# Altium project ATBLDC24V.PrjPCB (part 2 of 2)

## Sheet ATBLDC24V_Flash_Temp.SchDoc: ATBLDC24V_schematic
size A3; Organization: ATMEL Chennai; Address1: 12th Floor; Address2: Prince Infocity II; Address3: 283 & 284 OMR; Revision: 2; SheetNumber: 8; SheetTotal: 9; CheckedBy: MSK; DrawnBy: SAN/OJS; Engineer: SAN/OJS; PageSetup: Record=PageOptions¦CenterHorizontal=True¦CenterVertical=True¦PrintScale=1.01¦XCorrection=1.00¦YCorrection=1.00¦PrintKind=1¦BorderSize=5000000¦LeftOffset=0¦BottomOffset=0¦Orientation=2¦PaperLength=1000¦PaperWidth=1000¦Scale=100¦PaperSource=7¦PrintQuality=-4¦MediaType=1¦DitherType=10¦PaperKind=A3 (297 x 420 mm)¦PrintScaleMode=1
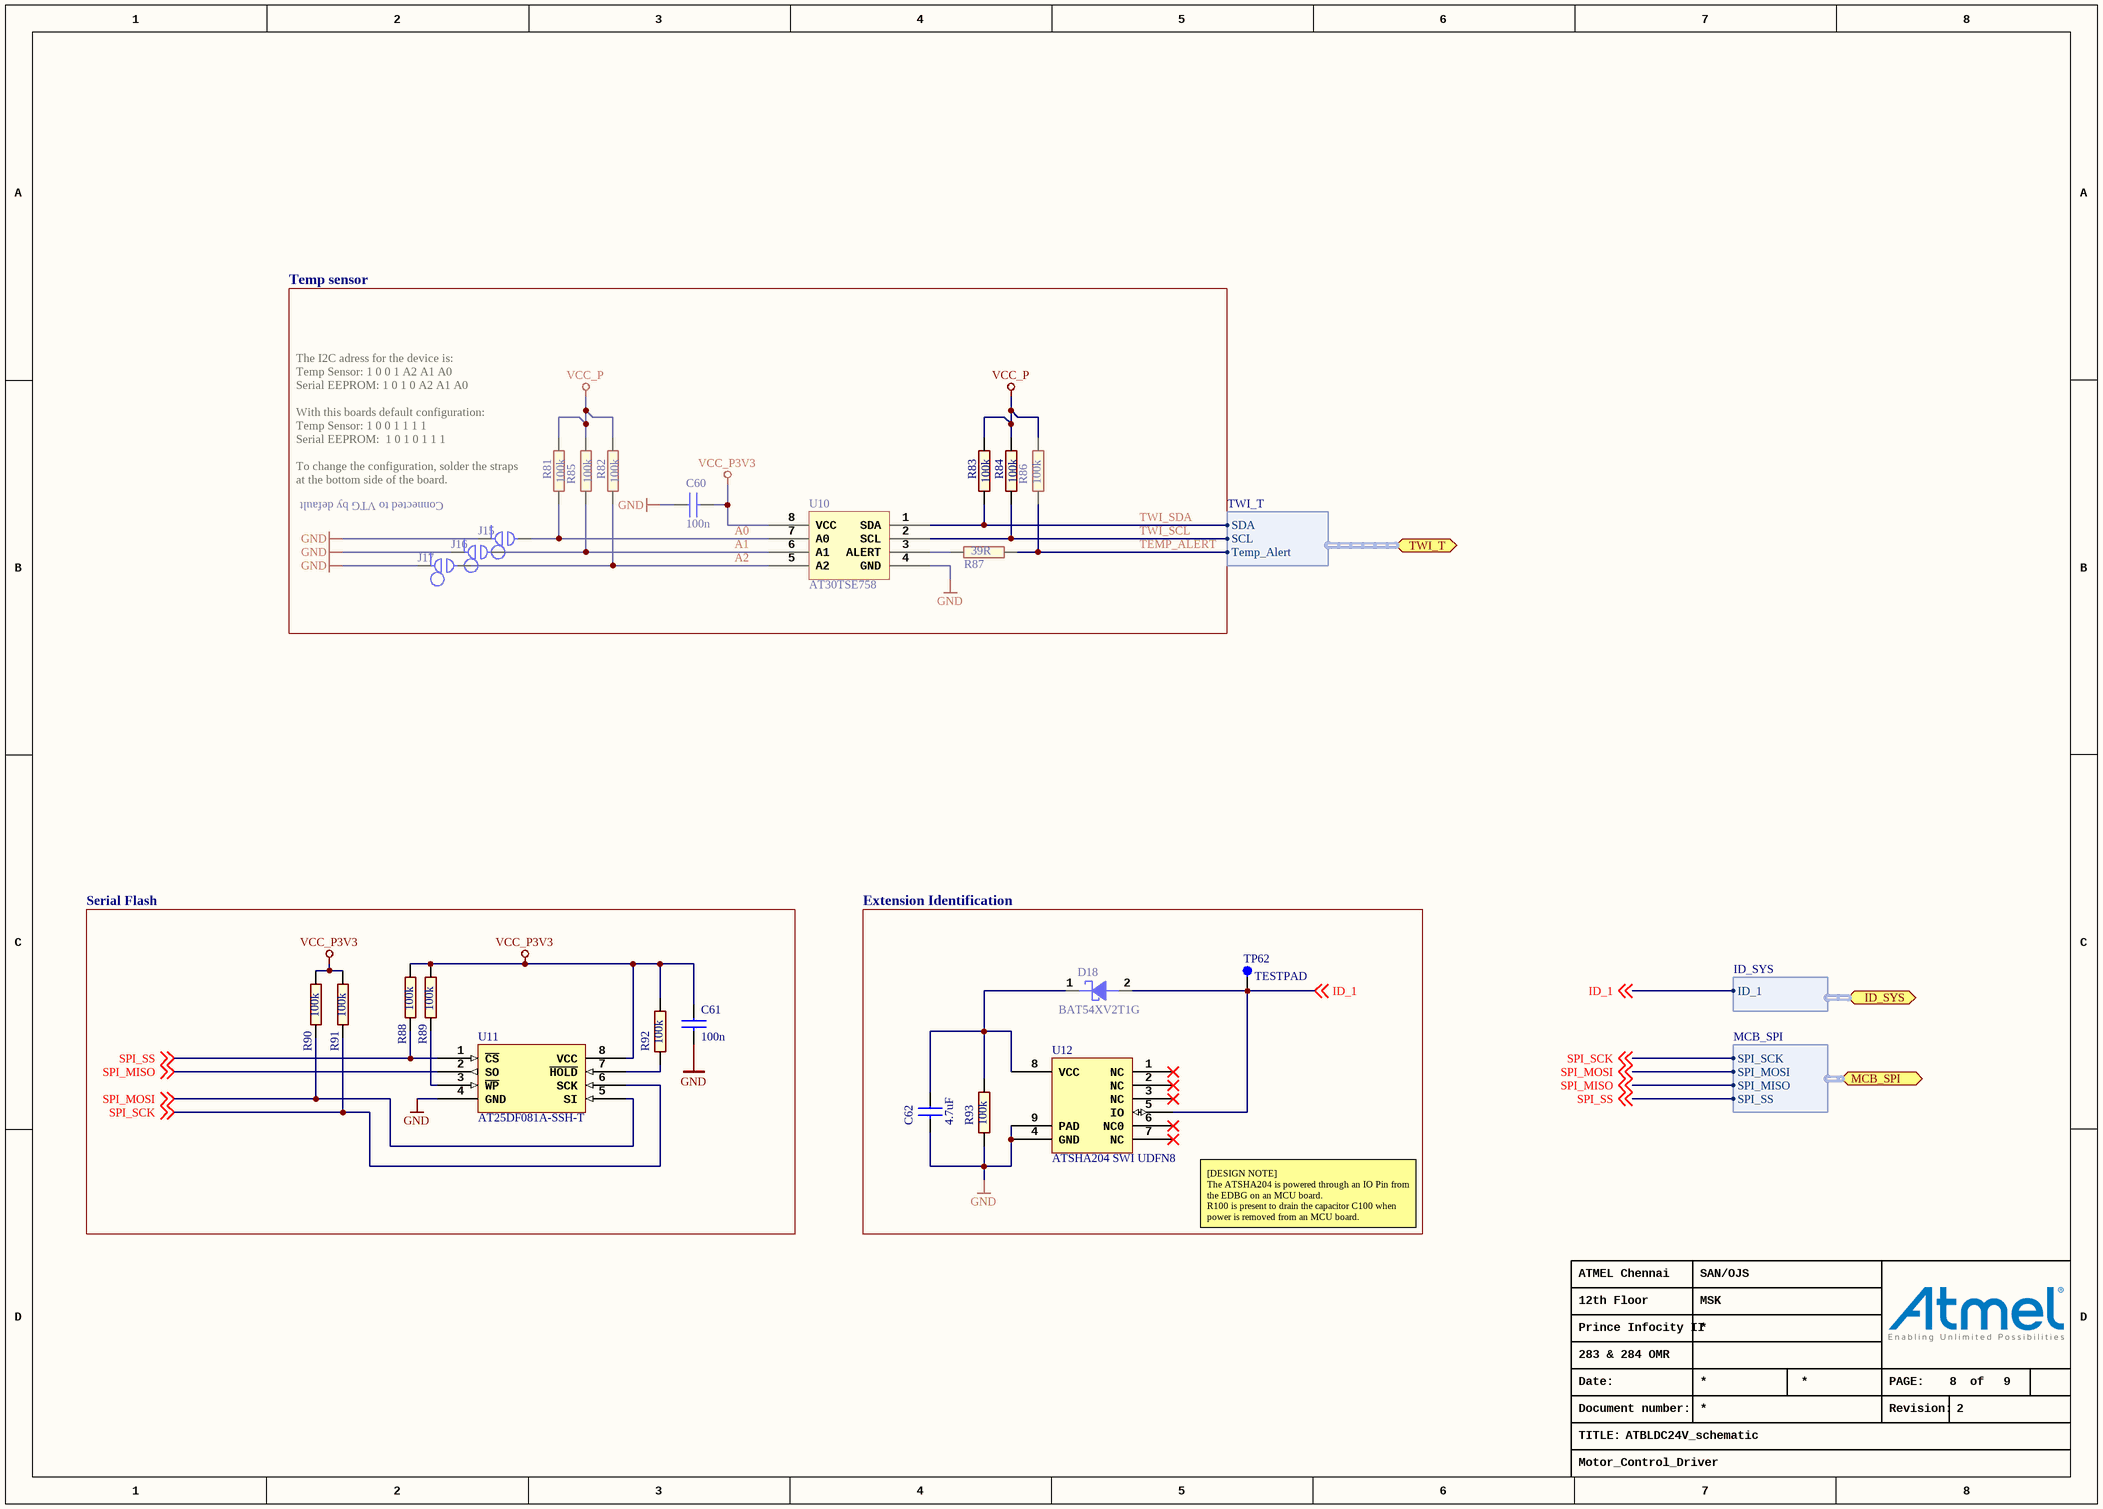
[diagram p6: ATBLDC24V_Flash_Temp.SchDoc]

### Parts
C60  100n  [AP1-00001]
C61  100n  [AP1-00001]
C62  value 4.7uF  [AP1-00001]  (hidden comment: Recommended by Escatec. No datasheet available yet.)
D18  value BAT54XV2T1G  [AP4-00036]  (hidden comment: Farnell# 1615809)
J15  Open Link  [AP9-00078]  (value not drawn)  (net tie, no BOM)
J16  Open Link  [AP9-00078]  (value not drawn)  (net tie, no BOM)
J17  Open Link  [AP9-00078]  (value not drawn)  (net tie, no BOM)
R81  value 100k  [AP2-00000]  (hidden comment: R2)
R82  value 100k  [AP2-00000]  (hidden comment: R2)
R83  value 100k  [AP2-00000]  (hidden comment: R2)
R84  value 100k  [AP2-00000]  (hidden comment: R2)
R85  value 100k  [AP2-00000]  (hidden comment: R2)
R86  value 100k  [AP2-00000]  (hidden comment: R2)
R87  value 39R  [AP2-00000]  (hidden comment: R2)
R88  value 100k  [AP2-00000]  (hidden comment: R2)
R89  value 100k  [AP2-00000]  (hidden comment: R2)
R90  value 100k  [AP2-00000]  (hidden comment: R2)
R91  value 100k  [AP2-00000]  (hidden comment: R2)
R92  value 100k  [AP2-00000]  (hidden comment: R2)
R93  value 100k  [AP2-00000]  (hidden comment: R2)
TP62  value TESTPAD  [AP8-00010]  (hidden comment: TESTPOINT)  (no BOM)
U10  value AT30TSE758  [AP6-00186]  (hidden comment: AT30TSx75x)
U11  value AT25DF081A-SSH-T  [AP8-00417]  (hidden comment: AT25DF081A)
U12  value ATSHA204 SWI UDFN8  [AP6-00409]  (hidden comment: ATSHA204A-SWI)

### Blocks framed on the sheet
Temp sensor: C60 J15-J17 R81-R87 U10
Serial Flash: C61 R88-R92 U11
Extension Identification: C62 D18 R93 TP62 U12

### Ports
ID_SYS (harness ID_SYS), MCB_SPI (harness MCB_SPI), TWI_T (harness TWI_T)

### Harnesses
TWI_T: SDA, SCL, Temp_Alert
MCB_SPI: SPI_SCK, SPI_MOSI, SPI_MISO, SPI_SS
ID_SYS: ID_1

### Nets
GND: C60.1 C61.2 C62.2 J15.1 J16.1 J17.1 R93.1 U10.4(GND) U10.9(GND) U11.4(GND) U12.4(GND) U12.9(PAD)
VCC_P: R81.1 R82.1 R83.1 R84.1 R85.1 R86.1
VCC_P3V3: C60.2 C61.1 R88.1 R89.1 R90.1 R91.1 R92.2 U10.8(VCC) U11.8(VCC)
A0: J15.2 R81.2 U10.7(A0)
A1: J16.2 R85.2 U10.6(A1)
A2: J17.2 R82.2 U10.5(A2)
ID_1: D18.2(ANODE) TP62.1 U12.5(IO) ; off-sheet ID_1, port ID_SYS.ID_1  [project net EDBG_ID1]
SPI_MISO: U11.2(SO) ; off-sheet SPI_MISO, port MCB_SPI.SPI_MISO
SPI_MOSI: R90.2 U11.5(SI) ; off-sheet SPI_MOSI, port MCB_SPI.SPI_MOSI
SPI_SCK: R91.2 U11.6(SCK) ; off-sheet SPI_SCK, port MCB_SPI.SPI_SCK
SPI_SS: R88.2 U11.1(~{CS}) ; off-sheet SPI_SS, port MCB_SPI.SPI_SS
TEMP_ALERT: R86.2 R87.2 ; port TWI_T.Temp_Alert  [project net GPIO7]
TWI_SCL: R84.2 U10.2(SCL) ; port TWI_T.SCL
TWI_SDA: R83.2 U10.1(SDA) ; port TWI_T.SDA
NetC62_1: C62.1 D18.1(CATHODE) R93.2 U12.8(VCC)
NetR87_1: R87.1 U10.3(ALERT)
NetR89_2: R89.2 U11.3(~{WP})
NetR92_1: R92.1 U11.7(~{HOLD})

Not connected (* = marked no-connect by the designer): U12 1(NC)* 2(NC)* 3(NC)* 6(NC0)* 7(NC)*

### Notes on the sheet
- The I2C adress for the device is:
  Temp Sensor:	1 0 0 1 A2 A1 A0
  Serial EEPROM:	1 0 1 0 A2 A1 A0
  With this boards default configuration:
  Temp Sensor:	1 0 0 1 1 1 1
  Serial EEPROM: 	1 0 1 0 1 1 1
  To change the configuration, solder the straps at the bottom side of the board.
- Connected to VTG by default
- [DESIGN NOTE]
  The ATSHA204 is powered through an IO Pin from the EDBG on an MCU board.
  R100 is present to drain the capacitor C100 when power is removed from an MCU board.

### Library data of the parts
C60 C61 = A01-0246: Ceramic capacitor, SMD 0402, X7R, 16V, +/-10%; PartGroup: Capacitors,Ceramic,SMD 0402; Manufacturer: Kemet; MPN: C0402C104K4RACTU; TemperatureRange: -55 - +125 deg C
C62 = A01-0347: Ceramic capacitor, SMD 0402, X5R, 6.3V, +/-20% (de33687); PartGroup: Capacitors,Ceramic,SMD 0402; Manufacturer: Murata; MPN: GRM155R60J475ME87D; Tolerance: +-20%; TemperatureRange: -55°C to +85°C
D18 = A04-0049: Schottky diode, If:200mA, Vf:0.35V, Vrrm:30V, SOD-523; PartGroup: Diodes,Schottky; Manufacturer: ON Semiconductor; TemperatureRange: -55°C to +125°C
J15-J17 = A08-1416: PartGroup: Mechanical devices,PCB implemented components
R81-R85 R88-R93 = A02-0260: Thick film resistor, SMD 0402, 1/16W, 1%; PartGroup: Resistors,SMD,0402 1%; TemperatureRange: -55 - +125 deg C
R86 = A02-0260: Thick film resistor, SMD 0402, 1/16W, 1%; OrcadPartType: Resistors&SMD&0402 1%; TemperatureRange: -55 - +125 deg C; PowerConsumption: 0; InUse: 1
R87 = A02-0178: Thick film resistor, SMD 0402, 1/16W, 1%; PartGroup: Resistors,SMD,0402 1%; TemperatureRange: -55 - +125 deg C
TP62 = A08-0004: Single SMD testpad; PartGroup: Mechanical devices,Connectors,Test points
U10 = A06-0633: SINGLE DIGITAL TEMPERATURE SENSOR W/ SERIAL EEPROM, UDFN8; PartGroup: Integrated Circuits,Sensors; Manufacturer: ATMEL; MPN: AT30TSE758-MA8-T
U11 = A06-1051: 8Mbit SPI serial flash memory; PartGroup: Integrated Circuits,Memory,FLASH; Manufacturer: Adesto Technologies; TemperatureRange: -40°C to +85°C
U12 = A06-1276: ATSHA204 with 1-wire interface and UDFN8 package; PartGroup: Integrated Circuits,Special function,Encryption; Manufacturer: ATMEL; MPN: ATSHA204A-MAHCZ-T

## Sheet ATBLDC24V_triple_input_power_supply.SchDoc: ATBLDC24V_Schematic
size A3; Organization: ATMEL Chennai; Address1: 12th Floor; Address2: Prince Infocity II; Address3: 283 & 284, OMR,; Address4: Chennai; Revision: 2; SheetNumber: 3; SheetTotal: 9; CheckedBy: MSK; DrawnBy: SAN/OJS; Engineer: SAN/OJS; PageSetup: Record=PageOptions¦CenterHorizontal=True¦CenterVertical=True¦PrintScale=1.01¦XCorrection=1.00¦YCorrection=1.00¦PrintKind=1¦BorderSize=5000000¦LeftOffset=0¦BottomOffset=0¦Orientation=2¦PaperLength=1000¦PaperWidth=1000¦Scale=100¦PaperSource=7¦PrintQuality=-4¦MediaType=1¦DitherType=10¦PaperKind=A3 (297 x 420 mm)¦PrintScaleMode=1
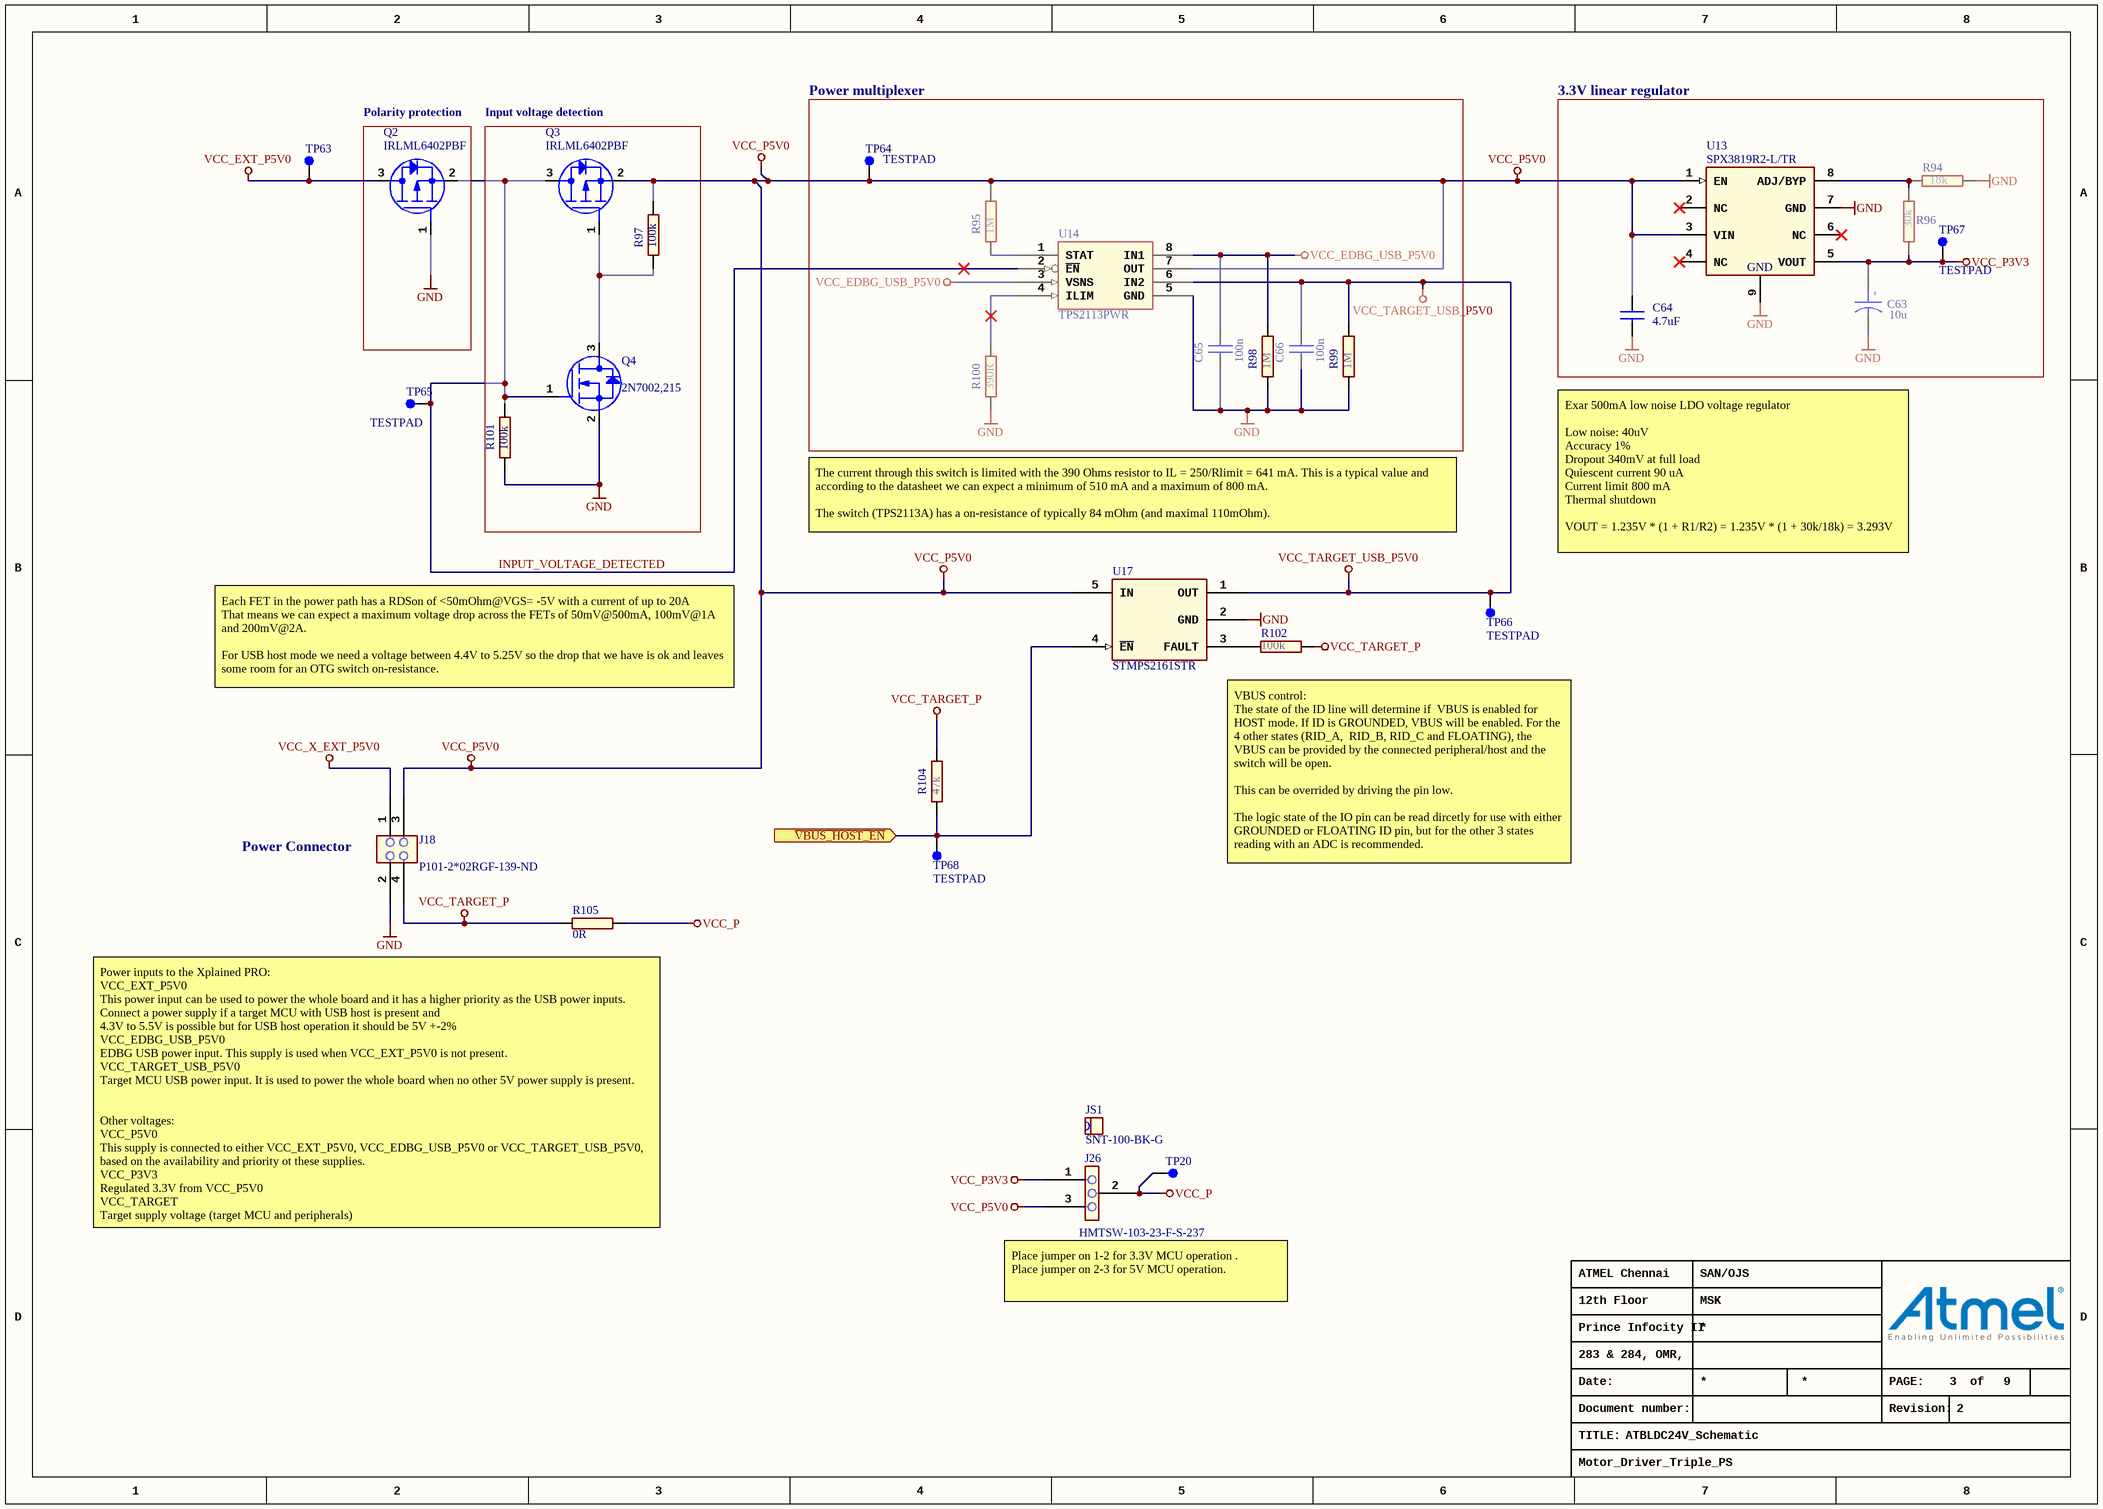
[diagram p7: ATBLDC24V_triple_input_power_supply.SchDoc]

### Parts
C63  value 10u  [AP1-00036]  (hidden comment: CAP-POL)
C64  value 4.7uF  [AP1-00039]  (hidden comment: CAP-NONPOL)
C65  value 100n  [AP1-00001]  (hidden comment: CAP-NONPOL)
C66  value 100n  [AP1-00001]  (hidden comment: CAP-NONPOL)
J18  value P101-2*02RGF-139-ND  [AP8-00628]  (hidden comment: HEADER 2x2)
J26  value HMTSW-103-23-F-S-237  [AP8-00745]  (hidden comment: Same as A08-1614 but with 1mm hole for optimal reflow soldering (no misalignment of the component))
JS1  value SNT-100-BK-G  [AP8-00525]  (hidden comment: To be used by request from ESCATEC)
Q2  value IRLML6402PBF  [AP5-00002]  (hidden comment: MOSFET_P_GSD)
Q3  value IRLML6402PBF  [AP5-00002]  (hidden comment: MOSFET_P_GSD)
Q4  value 2N7002,215  [AP5-00002]  (hidden comment: MOSFET_N_GSD)
R94  value 18k  [AP2-00000]  (hidden comment: R2)
R95  value 1M  [AP2-00000]  (hidden comment: R2)
R96  value 30k  [AP2-00000]  (hidden comment: R2)
R97  value 100k  [AP2-00000]  (hidden comment: R2)
R98  value 1M  [AP2-00000]  (hidden comment: R2)
R99  value 1M  [AP2-00000]  (hidden comment: R2)
R100  value 390R  [AP2-00000]  (hidden comment: R2)
R101  value 100k  [AP2-00000]  (hidden comment: R2)
R102  value 100k  [AP2-00000]  (hidden comment: R2)
R104  value 47k  [AP2-00000]  (hidden comment: R2)
R105  value 0R  [AP2-00000]  (hidden comment: R2)
TP20  TESTPOINT  [AP8-00010]  (value not drawn)  (no BOM)
TP63  TESTPOINT  [AP8-00010]  (value not drawn)  (no BOM)
TP64  value TESTPAD  [AP8-00010]  (hidden comment: TESTPOINT)  (no BOM)
TP65  value TESTPAD  [AP8-00010]  (hidden comment: TESTPOINT)  (no BOM)
TP66  value TESTPAD  [AP8-00010]  (hidden comment: TESTPOINT)  (no BOM)
TP67  value TESTPAD  [AP8-00010]  (hidden comment: TESTPOINT)  (no BOM)
TP68  value TESTPAD  [AP8-00010]  (hidden comment: TESTPOINT)  (no BOM)
U13  value SPX3819R2-L/TR  [AP6-00338]  (hidden comment: Mouser: 1016-1588-2-ND)
U14  value TPS2113PWR  [AP6-00054]  (hidden comment: TPS2112)
U17  value STMPS2161STR  [AP6-00087]  (hidden comment: STMPS2161)

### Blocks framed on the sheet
Polarity protection: Q2
Input voltage detection: Q3 Q4 R97 R101
Power multiplexer: C65 C66 R95 R98-R100 TP64 U14
3.3V linear regulator: C63 C64 R94 R96 TP67 U13

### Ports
~{VBUS_HOST_EN} (in)

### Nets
GND: C63.2 C64.2 C65.2 C66.2 J18.2 Q2.1(G) Q4.2(S) R94.2 R98.1 R99.1 R100.1 R101.1 U13.7(GND) U13.9(GND) U14.5(GND) U17.2(GND)
VCC_EDBG_USB_P5V0: C65.1 R98.2 U14.3(VSNS) U14.8(IN1)
VCC_EXT_P5V0: Q2.3(D) TP63.1
VCC_P: J26.2 R105.2 TP20.1
VCC_P3V3: C63.1 J26.1 R96.1 TP67.1 U13.5(VOUT)
VCC_P5V0: C64.1 J18.3 J26.3 Q3.2(S) R95.2 R97.2 TP64.1 U13.1(EN) U13.3(VIN) U14.7(OUT) U17.5(IN)
VCC_TARGET_P: J18.4 R102.1 R104.2 R105.1
VCC_TARGET_USB_P5V0: C66.1 R99.2 TP66.1 U14.6(IN2) U17.1(OUT)
VCC_X_EXT_P5V0: J18.1
INPUT_VOLTAGE_DETECTED: Q2.2(S) Q3.3(D) Q4.1(G) R101.2 TP65.1 U14.2(~{EN})
TARGET_USB_ID: R104.1 TP68.1 U17.4(~{EN}) ; port ~{VBUS_HOST_EN}
NetQ3_1: Q3.1(G) Q4.3(D) R97.1
NetR94_1: R94.1 R96.2 U13.8(ADJ/BYP)
NetR95_1: R95.1 U14.1(STAT)
NetR100_2: R100.2 U14.4(ILIM)
NetR102_2: R102.2 U17.3(FAULT)

Not connected (* = marked no-connect by the designer): U13 2(NC)* 4(NC)* 6(NC)*

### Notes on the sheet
- The current through this switch is limited with the 390 Ohms resistor to IL = 250/Rlimit = 641 mA. This is a typical value and according to the datasheet we can expect a minimum of 510 mA and a maximum of 800 mA.
  The switch (TPS2113A) has a on-resistance of typically 84 mOhm (and maximal 110mOhm).
- Exar 500mA low noise LDO voltage regulator
  Low noise: 40uV
  Accuracy 1%
  Dropout 340mV at full load
  Quiescent current 90 uA
  Current limit 800 mA
  Thermal shutdown
  VOUT = 1.235V * (1 + R1/R2) = 1.235V * (1 + 30k/18k) = 3.293V
- Each FET in the power path has a RDSon of <50mOhm@VGS= -5V with a current of up to 20A
  That means we can expect a maximum voltage drop across the FETs of 50mV@500mA, 100mV@1A and 200mV@2A.
  For USB host mode we need a voltage between 4.4V to 5.25V so the drop that we have is ok and leaves some room for an OTG switch on-resistance.
- (near J18) Power Connector
- VBUS control:
  The state of the ID line will determine if  VBUS is enabled for HOST mode. If ID is GROUNDED, VBUS will be enabled. For the 4 other states (RID_A,  RID_B, RID_C and FLOATING), the VBUS can be provided by the connected peripheral/host and the switch will be open.
  This can be overrided by driving the pin low.
  The logic state of the IO pin can be read dircetly for use with either GROUNDED or FLOATING ID pin, but for the other 3 states reading with an ADC is recommended.
- (near R105) Power inputs to the Xplained PRO:
  VCC_EXT_P5V0
  This power input can be used to power the whole board and it has a higher priority as the USB power inputs. Connect a power supply if a target MCU with USB host is present and
  4.3V to 5.5V is possible but for USB host operation it should be 5V +-2%
  VCC_EDBG_USB_P5V0
  EDBG USB power input. This supply is used when VCC_EXT_P5V0 is not present.
  VCC_TARGET_USB_P5V0
  Target MCU USB power input. It is used to power the whole board when no other 5V power supply is present.
  Other voltages:
  VCC_P5V0
  This supply is connected to either VCC_EXT_P5V0, VCC_EDBG_USB_P5V0 or VCC_TARGET_USB_P5V0, based on the availability and priority ot these supplies.
  VCC_P3V3
  Regulated 3.3V from VCC_P5V0
  VCC_TARGET
  Target supply voltage (target MCU and peripherals)
- (near J26) Place jumper on 1-2 for 3.3V MCU operation .
  Place jumper on 2-3 for 5V MCU operation.

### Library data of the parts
C63 = A01-0324: SMD tantalum capacitor, ESR = 1.7, 3216-18 (EIA) 1206,; PartGroup: Capacitors,Tantalum; Manufacturer: vishay; MPN: TR3A106K016C1700; Tolerance: +-10%; TemperatureRange: -55°C ~ 85°C
C64 = A01-0377: Ceramic capacitor, SMD 0603, X5R, 10V, 10% (de31036); PartGroup: Capacitors,Ceramic,SMD 0603; Manufacturer: tdk; MPN: C1608X5R1A475K; TemperatureRange: -55 - +85 deg C
C65 C66 = A01-0246: as C60 on sheet ATBLDC24V_Flash_Temp
J18 = A08-1519: Pin header, 2x2, Right Angle, 2.54mm, THT, Pin In Paste; PartGroup: Mechanical devices,Connectors,Pin headers
J26 = A08-1799: 1x3 pin header, 2.54mm pitch, Pin-in-Paste THM, 1mm hole; PartGroup: Mechanical devices,Connectors,Pin headers; Manufacturer: SAMTEC
JS1 = A08-0543: Jumper cap for 2.54mm pinheader; PartGroup: Mechanical devices,Mounting accessories,Other; Manufacturer: SAMTEC
Q2 Q3 = A05-0087: P-ch. MOSFET. -30V, -3.7A continuous,RDS(ON)=0.05Ohm@VGS=-4,5V, RDS(ON)=0.08Ohm@VGS=-2.5V; PartGroup: Transistors,Power FET,SMD; Manufacturer: International Rectifier; TemperatureRange: -55 - +150 deg C
Q4 = A05-0085: N-Channel MOSFET. 60V, 0.300A continuous, 1.2A Peak. RDS(ON) = 3.8Ohm@VGS=4.5V, VGS(th)<2.5V; PartGroup: Transistors,Small signal FET,SMD; Manufacturer: NXP; TemperatureRange: -65 to 150 deg C
R94 = A02-0242: Thick film resistor, SMD 0402, 1/16W, 1%; PartGroup: Resistors,SMD,0402 1%; TemperatureRange: -55 - +125 deg C
R95 R98 R99 = A02-0284: Thick film resistor, SMD 0402, 1/16W, 1%; PartGroup: Resistors,SMD,0402 1%; TemperatureRange: -55 - +125 deg C
R96 = A02-0247: Thick film resistor, SMD 0402, 1/16W, 1%; PartGroup: Resistors,SMD,0402 1%; TemperatureRange: -55 - +125 deg C
R97 R101 = A02-0260: as R81 on sheet ATBLDC24V_Flash_Temp
R100 = A02-0202: Thick film resistor, SMD 0402, 1/16W, 1%; PartGroup: Resistors,SMD,0402 1%; TemperatureRange: -55 - +125 deg C
R102 = A02-0260: Thick film resistor, SMD 0402, 1/16W, 1%; PartGroup: Resistors,SMD,0402 1%; TemperatureRange: -55ï¿½ to +125ï¿½C
R104 = A02-0252: Thick film resistor, SMD 0402, 1/16W, 1%; PartGroup: Resistors,SMD,0402 1%; TemperatureRange: -55 - +125 deg C
R105 = A02-0163: Thick film resistor, SMD 0402, 1/16W, 1%; PartGroup: Resistors,SMD,0402 1%; TemperatureRange: -55 - +125 deg C
TP20 TP63-TP68 = A08-0004: as TP62 on sheet ATBLDC24V_Flash_Temp
U13 = A06-0957: 500mA LDO, ADJ, low noise, 8-DFN package; PartGroup: Integrated Circuits,Regulators,Linear; Manufacturer: Exar; Tolerance: ±1%; TemperatureRange: -40°C to +125°C
U14 = A06-0068: Autoswitching 2:1 Power Mux; PartGroup: Integrated Circuits,General linear,Analog switch, bus switch and MUX; Manufacturer: Texas Instruments; TemperatureRange: -40 - + 125 deg C
U17 = A06-1087: Single channel power switch, 1A, reverse block, active low enabled.; PartGroup: Integrated Circuits,General linear,Analog switch, bus switch and MUX; Tolerance: 2.7 to 5.5V; TemperatureRange: -40Â°C to +85Â°C

## Sheet ATBLDC24V_Hall_Encoder.SchDoc: ATBLDC24V_schematic
size A3; Organization: ATMEL Chennai; Address1: 12th Floor; Address2: Prince Infocity II; Address3: 283 & 284 OMR; Revision: 5; SheetNumber: 7; SheetTotal: 9; CheckedBy: MSK; DrawnBy: SAN/OJS; Engineer: SAN/OJS; PageSetup: Record=PageOptions¦CenterHorizontal=True¦CenterVertical=True¦PrintScale=1.01¦XCorrection=1.00¦YCorrection=1.00¦PrintKind=1¦BorderSize=5000000¦LeftOffset=0¦BottomOffset=0¦Orientation=2¦PaperLength=1000¦PaperWidth=1000¦Scale=100¦PaperSource=7¦PrintQuality=-4¦MediaType=1¦DitherType=10¦PaperKind=A3 (297 x 420 mm)¦PrintScaleMode=1
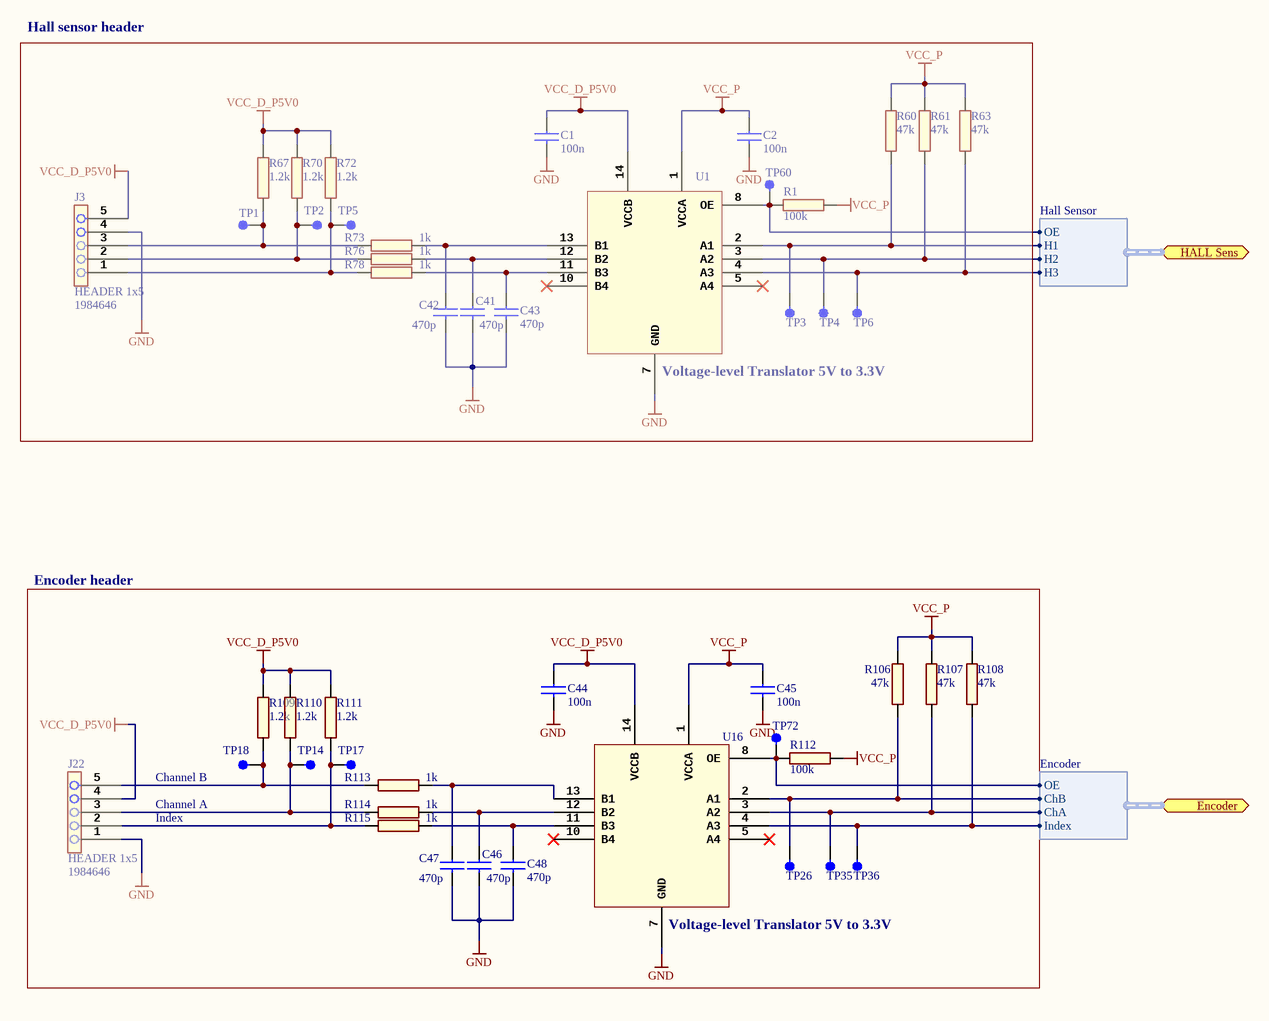
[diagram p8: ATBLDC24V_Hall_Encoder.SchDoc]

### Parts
C1  value 100n  [AP1-00002]  (hidden comment: CAP-NONPOL)
C2  value 100n  [AP1-00002]  (hidden comment: CAP-NONPOL)
C41  value 470p  [AP1-00002]  (hidden comment: MPN back-ported from Escatec 29-09-2009)
C42  value 470p  [AP1-00002]  (hidden comment: MPN back-ported from Escatec 29-09-2009)
C43  value 470p  [AP1-00002]  (hidden comment: MPN back-ported from Escatec 29-09-2009)
C44  value 100n  [AP1-00002]  (hidden comment: CAP-NONPOL)
C45  value 100n  [AP1-00002]  (hidden comment: CAP-NONPOL)
C46  value 470p  [AP1-00002]  (hidden comment: MPN back-ported from Escatec 29-09-2009)
C47  value 470p  [AP1-00002]  (hidden comment: MPN back-ported from Escatec 29-09-2009)
C48  value 470p  [AP1-00002]  (hidden comment: MPN back-ported from Escatec 29-09-2009)
J3  HEADER 1x5  value 1984646  [AP8-00935]
J22  HEADER 1x5  value 1984646  [AP8-00935]
R1  value 100k  [AP2-00000]  (hidden comment: R2)
R60  value 47k  [AP2-00001]  (hidden comment: R2)
R61  value 47k  [AP2-00001]  (hidden comment: R2)
R63  value 47k  [AP2-00001]  (hidden comment: R2)
R67  value 1.2k  [AP2-00001]  (hidden comment: R2)
R70  value 1.2k  [AP2-00001]  (hidden comment: R2)
R72  value 1.2k  [AP2-00001]  (hidden comment: R2)
R73  value 1k  [AP2-00000]  (hidden comment: R2)
R76  value 1k  [AP2-00000]  (hidden comment: R2)
R78  value 1k  [AP2-00000]  (hidden comment: R2)
R106  value 47k  [AP2-00001]  (hidden comment: R2)
R107  value 47k  [AP2-00001]  (hidden comment: R2)
R108  value 47k  [AP2-00001]  (hidden comment: R2)
R109  value 1.2k  [AP2-00001]  (hidden comment: R2)
R110  value 1.2k  [AP2-00001]  (hidden comment: R2)
R111  value 1.2k  [AP2-00001]  (hidden comment: R2)
R112  value 100k  [AP2-00000]  (hidden comment: R2)
R113  value 1k  [AP2-00000]  (hidden comment: R2)
R114  value 1k  [AP2-00000]  (hidden comment: R2)
R115  value 1k  [AP2-00000]  (hidden comment: R2)
TP1  TESTPOINT  [AP8-00010]  (value not drawn)  (no BOM)
TP2  TESTPOINT  [AP8-00010]  (value not drawn)  (no BOM)
TP3  Through hole with 10mil annular ring  [AP8-00722]  (value not drawn)  (no BOM)
TP4  Through hole with 10mil annular ring  [AP8-00722]  (value not drawn)  (no BOM)
TP5  TESTPOINT  [AP8-00010]  (value not drawn)  (no BOM)
TP6  Through hole with 10mil annular ring  [AP8-00722]  (value not drawn)  (no BOM)
TP14  TESTPOINT  [AP8-00010]  (value not drawn)  (no BOM)
TP17  TESTPOINT  [AP8-00010]  (value not drawn)  (no BOM)
TP18  TESTPOINT  [AP8-00010]  (value not drawn)  (no BOM)
TP26  Through hole with 10mil annular ring  [AP8-00722]  (value not drawn)  (no BOM)
TP35  Through hole with 10mil annular ring  [AP8-00722]  (value not drawn)  (no BOM)
TP36  Through hole with 10mil annular ring  [AP8-00722]  (value not drawn)  (no BOM)
TP60  TESTPOINT  [AP8-00010]  (value not drawn)  (no BOM)
TP72  TESTPOINT  [AP8-00010]  (value not drawn)  (no BOM)
U1  4Bit_BiDir_VLT  [AP6-00057]  (value not drawn)
U16  4Bit_BiDir_VLT  [AP6-00057]  (value not drawn)

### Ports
Encoder (harness Encoder), HALL Sens (harness Hall Sensor)

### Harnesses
Hall Sensor: H1, H2, H3, OE
Encoder: ChB, ChA, Index, OE

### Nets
GND: C1.2 C2.2 C41.2 C42.2 C43.2 C44.2 C45.2 C46.2 C47.2 C48.2 J3.4 J22.1 U1.7(GND) U16.7(GND)
VCC_D_P5V0: C1.1 C44.1 J3.5 J22.4 R67.2 R70.2 R72.2 R109.2 R110.2 R111.2 U1.14(VCCB) U16.14(VCCB)
VCC_P: C2.1 C45.1 R1.2 R60.2 R61.2 R63.2 R106.2 R107.2 R108.2 R112.2 U1.1(VCCA) U16.1(VCCA)
ENCODER_A: R107.1 TP35.1 U16.3(A2) ; port Encoder.ChA
ENCODER_B: R106.1 TP26.1 U16.2(A1) ; port Encoder.ChB
ENCODER_EN: R112.1 TP72.1 U16.8(OE) ; port Encoder.OE
ENCODER_Z: R108.1 TP36.1 U16.4(A3) ; port Encoder.Index
HALL1: R60.1 TP3.1 U1.2(A1) ; port HALL Sens.H1
HALL2: R61.1 TP4.1 U1.3(A2) ; port HALL Sens.H2
HALL3: R63.1 TP6.1 U1.4(A3) ; port HALL Sens.H3
HALL_TRX_OE: R1.1 TP60.1 U1.8(OE) ; port HALL Sens.OE
NetC41_1: C41.1 R76.2 U1.12(B2)
NetC42_1: C42.1 R73.2 U1.13(B1)
NetC43_1: C43.1 R78.2 U1.11(B3)
NetC46_1: C46.1 R114.2 U16.12(B2)
NetC47_1: C47.1 R113.2 U16.13(B1)
NetC48_1: C48.1 R115.2 U16.11(B3)
NetJ3_1: J3.1 R72.1 R78.1 TP5.1
NetJ3_2: J3.2 R70.1 R76.1 TP2.1
NetJ3_3: J3.3 R67.1 R73.1 TP1.1
NetJ22_2: J22.2 R111.1 R115.1 TP17.1
NetJ22_3: J22.3 R110.1 R114.1 TP14.1
NetJ22_5: J22.5 R109.1 R113.1 TP18.1

Not connected (* = marked no-connect by the designer): U1 5(A4)* 10(B4)*; U16 5(A4)* 10(B4)*

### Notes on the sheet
- Hall sensor header
- (near U1) Voltage-level Translator 5V to 3.3V
- Encoder header
- Index
- Channel A
- Channel B
- (near U16) Voltage-level Translator 5V to 3.3V

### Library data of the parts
C1 C2 C44 C45 = A01-0087: Ceramic capacitor, SMD 0603, X7R, 16V, +/-10 %; PartGroup: Capacitors,Ceramic,SMD 0603; Manufacturer: AVX; MPN: 0603YC104KAT2A; TemperatureRange: -55 - +125 deg C
C41-C43 C46-C48 = A01-0083: Ceramic capacitor, SMD 0603, NP0, 50V,  ±5 %; PartGroup: Capacitors,Ceramic,SMD 0603; Manufacturer: Pan Overseas; MPN: U0603C471JCT; Tolerance: 50V,  ±5 %; TemperatureRange: -55 - +125 deg C
J3 J22 = A08-2349: SCREW-TERMINAL 5-POLE, 3.5MM, Through Hole; PartGroup: Mechanical devices,Connectors,PCB - receptacle; Manufacturer: Phoenix Contacts
R1 R112 = A02-0260: as R102 on sheet ATBLDC24V_triple_input_power_supply
R60 R61 R63 R106-R108 = A02-0114: Thick film resistor, SMD 0603, 1/10W, 1%; PartGroup: Resistors,SMD,0603 1%
R67 R70 R72 R109-R111 = A02-0076: Thick film resistor, SMD 0603, 1/10W, 1%; PartGroup: Resistors,SMD,0603 1%
R73 R76 R78 R113-R115 = A02-0212: Thick film resistor, SMD 0402, 1/16W, 1%; PartGroup: Resistors,SMD,0402 1%; TemperatureRange: -55 - +125 deg C; ComponentStatus: 'Active (verified)'
TP1 TP2 TP5 TP14 TP17 TP18 TP60 TP72 = A08-0004: as TP62 on sheet ATBLDC24V_Flash_Temp
TP3 TP4 TP6 TP26 TP35 TP36 = A08-1748: Single thru-hole testpin; PartGroup: Mechanical devices,Connectors,Test points; Value: 40mil Through Hole Testpoint
U1 U16 = A06-0852: 4-BIT BIDIRECTIONAL VOLTAGE-LEVEL TRANSLATOR 14TSSOP; PartGroup: Integrated Circuits,Interface ICs,Level translators; Manufacturer: Philips; Value: NTS0104PW

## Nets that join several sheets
GND: ATBLDC24V_Main_supply (38 pins), ATBLDC24V_Driver (33 pins), ATBLDC24V_Connector (14 pins), ATBLDC24V_Bemf_Sensor (12 pins), ATBLDC24V_MCU (J6.64 J6.65 J6.66 J6.67), ATBLDC24V_Flash_Temp (12 pins), ATBLDC24V_triple_input_power_supply (16 pins), ATBLDC24V_Hall_Encoder (14 pins)
GND_E: ATBLDC24V_Main_supply (D8.2 Q1.2), ATBLDC24V_Connector (CONN1.2)
VCC_D: ATBLDC24V_Main_supply (9 pins), ATBLDC24V_Driver (9 pins)
VCC_D_P5V0: ATBLDC24V_Main_supply (C28.1 SW1.2 TP11.1 U6.3), ATBLDC24V_Hall_Encoder (12 pins)
VCC_EDBG_USB_P5V0: ATBLDC24V_Connector (C31.1 L1.2), ATBLDC24V_MCU (J6.10), ATBLDC24V_triple_input_power_supply (C65.1 R98.2 U14.3 U14.8)
VCC_EXT_P5V0: ATBLDC24V_Main_supply (SW1.1), ATBLDC24V_triple_input_power_supply (Q2.3 TP63.1)
VCC_P: ATBLDC24V_Driver (6 pins), ATBLDC24V_Bemf_Sensor (C39.2 R54.2 U15.5), ATBLDC24V_MCU (J6.62 J6.63), ATBLDC24V_Flash_Temp (6 pins), ATBLDC24V_triple_input_power_supply (J26.2 R105.2 TP20.1), ATBLDC24V_Hall_Encoder (12 pins)
VCC_P3V3: ATBLDC24V_Connector (J2.20), ATBLDC24V_MCU (J6.59 J6.61), ATBLDC24V_Flash_Temp (9 pins), ATBLDC24V_triple_input_power_supply (5 pins)
VCC_P/2: ATBLDC24V_Driver (R44.1 R45.1 R50.1), ATBLDC24V_Bemf_Sensor (R55.2 TP15.1)
VCC_TARGET_USB_P5V0: ATBLDC24V_Connector (C55.1 L6.2), ATBLDC24V_MCU (J6.8), ATBLDC24V_triple_input_power_supply (5 pins)
VCC_X_EXT_P5V0: ATBLDC24V_Main_supply (SW1.3), ATBLDC24V_triple_input_power_supply (J18.1)
VDC_MOTOR: ATBLDC24V_Main_supply (C18.1 C20.1 F1.2), ATBLDC24V_Driver (9 pins), ATBLDC24V_Bemf_Sensor (R79.1 TP27.1)
BEMF_UADC: ATBLDC24V_Bemf_Sensor (5 pins), ATBLDC24V_MCU (J6.42)
BEMF_UP: ATBLDC24V_Bemf_Sensor (L2.2), ATBLDC24V_MCU (J6.45)
BEMF_VADC: ATBLDC24V_Bemf_Sensor (5 pins), ATBLDC24V_MCU (J6.43)
BEMF_VP: ATBLDC24V_Bemf_Sensor (L3.2), ATBLDC24V_MCU (J6.47)
BEMF_WADC: ATBLDC24V_Bemf_Sensor (5 pins), ATBLDC24V_MCU (J6.44)
BEMF_WP: ATBLDC24V_Bemf_Sensor (L4.2), ATBLDC24V_MCU (J6.49)
EDBG_ID1: ATBLDC24V_MCU (J6.6), ATBLDC24V_Flash_Temp (D18.2 TP62.1 U12.5)
EDBG_ID2: ATBLDC24V_Connector (J2.1), ATBLDC24V_MCU (J6.4)
EDBG_USB_HS_N: ATBLDC24V_Connector (D10.3 J4.2), ATBLDC24V_MCU (J6.3)
EDBG_USB_HS_P: ATBLDC24V_Connector (D10.2 J4.3), ATBLDC24V_MCU (J6.1)
ENCODER_A: ATBLDC24V_MCU (J6.55), ATBLDC24V_Hall_Encoder (R107.1 TP35.1 U16.3)
ENCODER_B: ATBLDC24V_MCU (J6.56), ATBLDC24V_Hall_Encoder (R106.1 TP26.1 U16.2)
ENCODER_EN: ATBLDC24V_MCU (J6.58), ATBLDC24V_Hall_Encoder (R112.1 TP72.1 U16.8)
ENCODER_Z: ATBLDC24V_MCU (J6.57), ATBLDC24V_Hall_Encoder (R108.1 TP36.1 U16.4)
GPIO7: ATBLDC24V_MCU (J6.24), ATBLDC24V_Flash_Temp (R86.2 R87.2)
GPIO8: ATBLDC24V_Main_supply (Q12.1 R121.2 TP45.1), ATBLDC24V_MCU (J6.25)
HALL1: ATBLDC24V_MCU (J6.51), ATBLDC24V_Hall_Encoder (R60.1 TP3.1 U1.2)
HALL2: ATBLDC24V_MCU (J6.52), ATBLDC24V_Hall_Encoder (R61.1 TP4.1 U1.3)
HALL3: ATBLDC24V_MCU (J6.53), ATBLDC24V_Hall_Encoder (R63.1 TP6.1 U1.4)
HALL_TRX_OE: ATBLDC24V_MCU (J6.54), ATBLDC24V_Hall_Encoder (R1.1 TP60.1 U1.8)
MOTOR_VDC: ATBLDC24V_Bemf_Sensor (5 pins), ATBLDC24V_MCU (J6.41)
NetCONN1_1: ATBLDC24V_Main_supply (5 pins), ATBLDC24V_Connector (CONN1.1)
NetJ2_3: ATBLDC24V_Connector (J2.3), ATBLDC24V_MCU (J19.1)
NetJ2_4: ATBLDC24V_Connector (J2.4), ATBLDC24V_MCU (J20.1)
NetJ2_5: ATBLDC24V_Connector (J2.5), ATBLDC24V_MCU (J8.1)
NetJ2_6: ATBLDC24V_Connector (J2.6), ATBLDC24V_MCU (J9.1)
NetJ2_7: ATBLDC24V_Connector (J2.7), ATBLDC24V_MCU (J13.1)
NetJ2_8: ATBLDC24V_Connector (J2.8), ATBLDC24V_MCU (J14.1)
NetJ2_9: ATBLDC24V_Connector (J2.9), ATBLDC24V_MCU (J21.1)
NetJ2_10: ATBLDC24V_Connector (J2.10), ATBLDC24V_MCU (J10.1)
NetJ2_13: ATBLDC24V_Connector (J2.13), ATBLDC24V_MCU (J12.1)
NetJ2_14: ATBLDC24V_Connector (J2.14), ATBLDC24V_MCU (J11.1)
NetJ2_15: ATBLDC24V_Connector (J2.15), ATBLDC24V_MCU (J7.1)
PA03_USB_ID: ATBLDC24V_Connector (R43.2), ATBLDC24V_MCU (J6.11)
PWM_UH: ATBLDC24V_Driver (R3.2 U2.2), ATBLDC24V_Connector (J1.6), ATBLDC24V_MCU (J6.28)
PWM_UL: ATBLDC24V_Driver (R4.1 U2.3), ATBLDC24V_Connector (J1.5), ATBLDC24V_MCU (J6.29)
PWM_VH: ATBLDC24V_Driver (R13.2 U3.2), ATBLDC24V_Connector (J1.4), ATBLDC24V_MCU (J6.30)
PWM_VL: ATBLDC24V_Driver (R14.1 U3.3), ATBLDC24V_Connector (J1.3), ATBLDC24V_MCU (J6.31)
PWM_WH: ATBLDC24V_Driver (R23.2 U4.2), ATBLDC24V_Connector (J1.2), ATBLDC24V_MCU (J6.32)
PWM_WL: ATBLDC24V_Driver (R24.1 U4.3), ATBLDC24V_Connector (J1.1), ATBLDC24V_MCU (J6.33)
Ref_BEMF_sens: ATBLDC24V_Bemf_Sensor (L5.2), ATBLDC24V_MCU (J23.1 J24.1 J25.1)
SPI_MISO: ATBLDC24V_Connector (J2.17), ATBLDC24V_MCU (J6.15), ATBLDC24V_Flash_Temp (U11.2)
SPI_MOSI: ATBLDC24V_Connector (J2.16), ATBLDC24V_MCU (J6.17), ATBLDC24V_Flash_Temp (R90.2 U11.5)
SPI_SCK: ATBLDC24V_Connector (J2.18), ATBLDC24V_MCU (J6.16), ATBLDC24V_Flash_Temp (R91.2 U11.6)
SPI_SS: ATBLDC24V_MCU (J6.14), ATBLDC24V_Flash_Temp (R88.2 U11.1)
TARGET_USB_HS_N: ATBLDC24V_Connector (D12.3 J5.2), ATBLDC24V_MCU (J6.9)
TARGET_USB_HS_P: ATBLDC24V_Connector (D12.2 J5.3), ATBLDC24V_MCU (J6.7)
TARGET_USB_ID: ATBLDC24V_Connector (J5.4 R43.1), ATBLDC24V_triple_input_power_supply (R104.1 TP68.1 U17.4)
TWI_SCL: ATBLDC24V_Connector (J2.12), ATBLDC24V_MCU (J6.13), ATBLDC24V_Flash_Temp (R84.2 U10.2)
TWI_SDA: ATBLDC24V_Connector (J2.11), ATBLDC24V_MCU (J6.12), ATBLDC24V_Flash_Temp (R83.2 U10.1)
U_emf: ATBLDC24V_Driver (8 pins), ATBLDC24V_Connector (CONN2.1), ATBLDC24V_Bemf_Sensor (R64.1)
USHUNT_ADC: ATBLDC24V_Driver (C34.2 R52.2 TP13.1 U8.1), ATBLDC24V_MCU (J6.38)
V_emf: ATBLDC24V_Driver (8 pins), ATBLDC24V_Connector (CONN2.2), ATBLDC24V_Bemf_Sensor (R68.1)
VSHUNT_ADC: ATBLDC24V_Driver (C33.2 R51.2 TP16.1 U7.1), ATBLDC24V_MCU (J6.39)
W_emf: ATBLDC24V_Driver (8 pins), ATBLDC24V_Connector (CONN2.3), ATBLDC24V_Bemf_Sensor (R74.1)
WSHUNT_ADC: ATBLDC24V_Driver (C37.2 R53.2 TP19.1 U9.1), ATBLDC24V_MCU (J6.40)

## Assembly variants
Default_assembly: not fitted TP8 TP9
ID powered through VTG: not fitted TP1 TP4 TP8 TP9 TP10 TP11 TP12 TP13
ATBLDC24V: not fitted C49 C50 C56 R7 R11 R17 R21 R27 R31 R36 R60 R61 R63 R90 R91 R106 R107 R108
